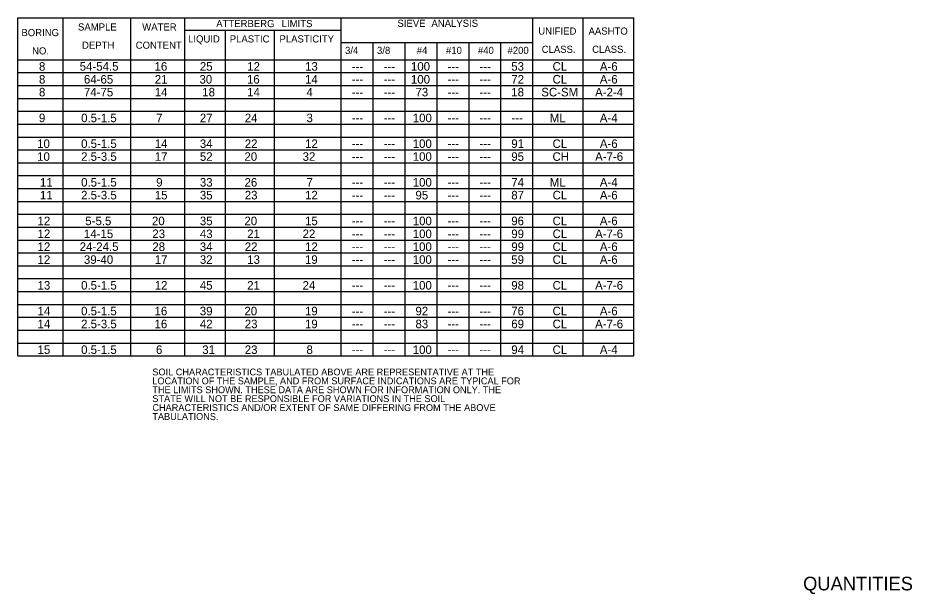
# Model space of a CAD drawing. Extents: x 1197542 to 1207464, y 185022 to 237324.
# Drawn here: x 1206911.8 to 1207068.6, y 185021.7 to 185122.8 of the extents above; entities that cross this region are included whole.
import ezdxf

# ---------------------------------------------------------------- set-up
doc = ezdxf.new("R2010")
doc.units = 0
doc.layers.add('R_Annotation', color=7, linetype='Continuous')
doc.layers.add('R_No Plot', color=7, linetype='Continuous')

msp = doc.modelspace()

# ---------------------------------------------------------------- linework, layer by layer
at = {"layer": 'R_No Plot'}
for p, q in [((1206911.83, 185122.77), (1206911.83, 185122.77)), ((1206911.83, 185122.77), (1207019.8, 185122.77)), ((1206911.83, 185063.47), (1206911.83, 185122.77)), ((1206919.77, 185063.47), (1206919.77, 185122.77)), ((1206931.61, 185063.47), (1206931.61, 185122.77)), ((1206941.11, 185063.47), (1206941.11, 185122.77)), ((1206968.54, 185063.47), (1206968.54, 185122.77)), ((1207002.13, 185063.47), (1207002.13, 185122.77)), ((1207010.96, 185063.47), (1207010.96, 185122.77)), ((1207019.8, 185063.47), (1207019.8, 185122.77)), ((1206941.11, 185120.6), (1206968.54, 185120.6)), ((1206948.26, 185063.47), (1206948.26, 185120.6)), ((1206956.84, 185063.47), (1206956.84, 185120.6)), ((1206968.54, 185118.44), (1207002.13, 185118.44)), ((1206974.14, 185063.47), (1206974.14, 185118.44)), ((1206979.74, 185063.47), (1206979.74, 185118.44)), ((1206985.34, 185063.47), (1206985.34, 185118.44)), ((1206990.94, 185063.47), (1206990.94, 185118.44)), ((1206996.53, 185063.47), (1206996.53, 185118.44)), ((1206911.83, 185115.42), (1207019.8, 185115.42)), ((1207002.13, 185115.42), (1207019.8, 185115.42)), ((1206911.83, 185113.16), (1207019.8, 185113.16)), ((1206911.83, 185110.9), (1207019.8, 185110.9)), ((1206911.83, 185108.64), (1207019.8, 185108.64)), ((1206911.83, 185106.39), (1207019.8, 185106.39)), ((1206911.83, 185104.13), (1207019.8, 185104.13)), ((1206911.83, 185101.87), (1207019.8, 185101.87)), ((1206911.83, 185099.61), (1207019.8, 185099.61)), ((1206911.83, 185097.35), (1207019.8, 185097.35)), ((1206911.83, 185095.09), (1207019.8, 185095.09)), ((1206911.83, 185092.83), (1207019.8, 185092.83)), ((1206911.83, 185090.57), (1207019.8, 185090.57)), ((1206911.83, 185088.32), (1207019.8, 185088.32)), ((1206911.83, 185086.06), (1207019.8, 185086.06)), ((1206911.83, 185083.8), (1207019.8, 185083.8)), ((1206911.83, 185081.54), (1207019.8, 185081.54)), ((1206911.83, 185079.28), (1207019.8, 185079.28)), ((1206911.83, 185077.02), (1207019.8, 185077.02)), ((1206911.83, 185074.76), (1207019.8, 185074.76)), ((1206911.83, 185072.5), (1207019.8, 185072.5)), ((1206911.83, 185070.25), (1207019.8, 185070.25)), ((1206911.83, 185067.99), (1207019.8, 185067.99)), ((1206911.83, 185065.73), (1207019.8, 185065.73)), ((1206911.83, 185063.47), (1207019.8, 185063.47))]:
    msp.add_line(p, q, dxfattribs=at)

# ---------------------------------------------------------------- texts
at = {"layer": 'R_Annotation'}
msp.add_text('QUANTITIES', height=2.4, rotation=360, dxfattribs=at).set_placement((1207049.51, 185022.34))
at = {"layer": 'R_No Plot'}
for s, height, p in [('ATTERBERG', 1.25, (1206946.61, 185121.14)), ('LIMITS', 1.25, (1206958.09, 185121.14)), ('SIEVE', 1.25, (1206978.38, 185121.19)), ('ANALYSIS', 1.25, (1206984.34, 185121.19)), ('BORING', 1.25, (1206912.45, 185119.56)), ('SAMPLE', 1.25, (1206922.38, 185120.55)), ('WATER', 1.25, (1206933.63, 185120.55)), ('UNIFIED', 1.25, (1207003.07, 185119.83)), ('AASHTO', 1.25, (1207011.89, 185119.83)), ('LIQUID', 1.25, (1206941.67, 185118.45)), ('PLASTIC', 1.25, (1206948.98, 185118.45)), ('PLASTICITY', 1.25, (1206957.7, 185118.45)), ('NO.', 1.25, (1206914.32, 185116.35)), ('DEPTH', 1.25, (1206923.08, 185117.35)), ('CONTENT', 1.25, (1206932.49, 185117.35)), ('3/4', 1.25, (1206969.2, 185116.44)), ('3/8', 1.25, (1206974.8, 185116.44)), ('#4', 1.25, (1206981.77, 185116.44)), ('#10', 1.25, (1206986.89, 185116.44)), ('#40', 1.25, (1206992.49, 185116.44)), ('#200', 1.25, (1206997.68, 185116.44)), ('CLASS.', 1.25, (1207003.67, 185116.63)), ('CLASS.', 1.25, (1207012.52, 185116.63)), ('8', 1.5, (1206915.53, 185113.5)), ('54-54.5', 1.5, (1206922.67, 185113.5)), ('16', 1.5, (1206935.79, 185113.5)), ('25', 1.5, (1206943.74, 185113.5)), ('12', 1.5, (1206952.04, 185113.5)), ('13', 1.5, (1206962.18, 185113.5)), ('100', 1.5, (1206980.75, 185113.5)), ('53', 1.5, (1206998.34, 185113.5)), ('CL', 1.5, (1207005.58, 185113.5)), ('A-6', 1.5, (1207013.87, 185113.5)), ('8', 1.5, (1206915.53, 185111.24)), ('64-65', 1.5, (1206923.41, 185111.24)), ('21', 1.5, (1206935.83, 185111.24)), ('30', 1.5, (1206943.67, 185111.24)), ('16', 1.5, (1206952, 185111.24)), ('14', 1.5, (1206962.18, 185111.24)), ('---', 1.5, (1206970.37, 185113.5)), ('---', 1.5, (1206975.97, 185113.5)), ('100', 1.5, (1206980.75, 185111.24)), ('---', 1.5, (1206987.17, 185113.5)), ('---', 1.5, (1206992.76, 185113.5)), ('72', 1.5, (1206998.34, 185111.24)), ('CL', 1.5, (1207005.58, 185111.24)), ('A-6', 1.5, (1207013.87, 185111.24)), ('---', 1.5, (1206970.37, 185111.24)), ('---', 1.5, (1206975.97, 185111.24)), ('---', 1.5, (1206987.17, 185111.24)), ('---', 1.5, (1206992.76, 185111.24)), ('8', 1.5, (1206915.53, 185108.99)), ('74-75', 1.5, (1206923.41, 185108.99)), ('14', 1.5, (1206935.83, 185108.99)), ('18', 1.5, (1206944.16, 185108.99)), ('14', 1.5, (1206952.04, 185108.99)), ('4', 1.5, (1206962.43, 185108.99)), ('---', 1.5, (1206970.37, 185108.99)), ('---', 1.5, (1206975.97, 185108.99)), ('73', 1.5, (1206981.54, 185108.99)), ('---', 1.5, (1206987.17, 185108.99)), ('---', 1.5, (1206992.76, 185108.99)), ('18', 1.5, (1206998.34, 185108.99)), ('SC-SM', 1.5, (1207003.6, 185108.99)), ('A-2-4', 1.5, (1207013.04, 185108.99)), ('9', 1.5, (1206915.52, 185104.47)), ('0.5-1.5', 1.5, (1206922.92, 185104.47)), ('7', 1.5, (1206936.08, 185104.47)), ('27', 1.5, (1206943.74, 185104.47)), ('24', 1.5, (1206951.61, 185104.47)), ('3', 1.5, (1206962.43, 185104.47)), ('---', 1.5, (1206970.37, 185104.47)), ('---', 1.5, (1206975.97, 185104.47)), ('100', 1.5, (1206981.06, 185104.47)), ('---', 1.5, (1206987.17, 185104.47)), ('---', 1.5, (1206992.76, 185104.47)), ('---', 1.5, (1206998.36, 185104.47)), ('ML', 1.5, (1207005.09, 185104.47)), ('A-4', 1.5, (1207013.87, 185104.47)), ('10', 1.5, (1206915.21, 185099.95)), ('0.5-1.5', 1.5, (1206922.92, 185099.95)), ('14', 1.5, (1206935.83, 185099.95)), ('34', 1.5, (1206943.74, 185099.95)), ('22', 1.5, (1206951.61, 185099.95)), ('12', 1.5, (1206962.18, 185099.95)), ('---', 1.5, (1206970.37, 185099.95)), ('---', 1.5, (1206975.97, 185099.95)), ('100', 1.5, (1206981.06, 185099.95)), ('---', 1.5, (1206987.17, 185099.95)), ('---', 1.5, (1206992.76, 185099.95)), ('91', 1.5, (1206998.34, 185099.95)), ('CL', 1.5, (1207005.58, 185099.95)), ('A-6', 1.5, (1207013.87, 185099.95)), ('10', 1.5, (1206915.21, 185097.69)), ('2.5-3.5', 1.5, (1206922.92, 185097.69)), ('17', 1.5, (1206935.83, 185097.69)), ('52', 1.5, (1206943.74, 185097.69)), ('20', 1.5, (1206951.55, 185097.69)), ('32', 1.5, (1206961.75, 185097.69)), ('100', 1.5, (1206981.06, 185097.69)), ('95', 1.5, (1206998.34, 185097.69)), ('CH', 1.5, (1207005.57, 185097.69)), ('A-7-6', 1.5, (1207013.04, 185097.69)), ('---', 1.5, (1206970.37, 185097.69)), ('---', 1.5, (1206975.97, 185097.69)), ('---', 1.5, (1206987.17, 185097.69)), ('---', 1.5, (1206992.76, 185097.69)), ('11', 1.5, (1206915.7, 185093.17)), ('0.5-1.5', 1.5, (1206922.92, 185093.17)), ('9', 1.5, (1206936.08, 185093.17)), ('33', 1.5, (1206943.74, 185093.17)), ('26', 1.5, (1206951.57, 185093.17)), ('7', 1.5, (1206962.43, 185093.17)), ('100', 1.5, (1206981.06, 185093.17)), ('74', 1.5, (1206998.34, 185093.17)), ('ML', 1.5, (1207005.09, 185093.17)), ('A-4', 1.5, (1207013.87, 185093.17)), ('11', 1.5, (1206915.7, 185090.92)), ('2.5-3.5', 1.5, (1206922.92, 185090.92)), ('15', 1.5, (1206935.83, 185090.92)), ('35', 1.5, (1206943.74, 185090.92)), ('23', 1.5, (1206951.61, 185090.92)), ('12', 1.5, (1206962.18, 185090.92)), ('---', 1.5, (1206970.37, 185093.17)), ('---', 1.5, (1206975.97, 185093.17)), ('95', 1.5, (1206981.54, 185090.92)), ('---', 1.5, (1206987.17, 185093.17)), ('---', 1.5, (1206992.76, 185093.17)), ('87', 1.5, (1206998.34, 185090.92)), ('CL', 1.5, (1207005.58, 185090.92)), ('A-6', 1.5, (1207013.87, 185090.92)), ('---', 1.5, (1206970.37, 185090.92)), ('---', 1.5, (1206975.97, 185090.92)), ('---', 1.5, (1206987.17, 185090.92)), ('---', 1.5, (1206992.76, 185090.92)), ('12', 1.5, (1206915.28, 185086.4)), ('5-5.5', 1.5, (1206923.65, 185086.4)), ('20', 1.5, (1206935.34, 185086.4)), ('35', 1.5, (1206943.74, 185086.4)), ('20', 1.5, (1206951.55, 185086.4)), ('15', 1.5, (1206962.18, 185086.4)), ('100', 1.5, (1206981.06, 185086.4)), ('96', 1.5, (1206998.34, 185086.4)), ('CL', 1.5, (1207005.58, 185086.4)), ('A-6', 1.5, (1207013.87, 185086.4)), ('---', 1.5, (1206970.37, 185086.4)), ('---', 1.5, (1206975.97, 185086.4)), ('---', 1.5, (1206987.17, 185086.4)), ('---', 1.5, (1206992.76, 185086.4)), ('12', 1.5, (1206915.28, 185084.14)), ('14-15', 1.5, (1206923.41, 185084.14)), ('23', 1.5, (1206935.41, 185084.14)), ('43', 1.5, (1206943.74, 185084.14)), ('21', 1.5, (1206952.04, 185084.14)), ('22', 1.5, (1206961.75, 185084.14)), ('---', 1.5, (1206970.37, 185084.14)), ('---', 1.5, (1206975.97, 185084.14)), ('100', 1.5, (1206981.06, 185084.14)), ('---', 1.5, (1206987.17, 185084.14)), ('---', 1.5, (1206992.76, 185084.14)), ('99', 1.5, (1206998.34, 185084.14)), ('CL', 1.5, (1207005.58, 185084.14)), ('A-7-6', 1.5, (1207013.04, 185084.14)), ('12', 1.5, (1206915.28, 185081.88)), ('24-24.5', 1.5, (1206922.67, 185081.88)), ('28', 1.5, (1206935.41, 185081.88)), ('34', 1.5, (1206943.74, 185081.88)), ('22', 1.5, (1206951.61, 185081.88)), ('12', 1.5, (1206962.18, 185081.88)), ('100', 1.5, (1206981.06, 185081.88)), ('99', 1.5, (1206998.34, 185081.88)), ('CL', 1.5, (1207005.58, 185081.88)), ('A-6', 1.5, (1207013.87, 185081.88)), ('---', 1.5, (1206970.37, 185081.88)), ('---', 1.5, (1206975.97, 185081.88)), ('---', 1.5, (1206987.17, 185081.88)), ('---', 1.5, (1206992.76, 185081.88)), ('12', 1.5, (1206915.28, 185079.62)), ('39-40', 1.5, (1206923.41, 185079.62)), ('17', 1.5, (1206935.83, 185079.62)), ('32', 1.5, (1206943.74, 185079.62)), ('13', 1.5, (1206952.04, 185079.62)), ('19', 1.5, (1206962.17, 185079.62)), ('---', 1.5, (1206970.37, 185079.62)), ('---', 1.5, (1206975.97, 185079.62)), ('100', 1.5, (1206981.06, 185079.62)), ('---', 1.5, (1206987.17, 185079.62)), ('---', 1.5, (1206992.76, 185079.62)), ('59', 1.5, (1206998.34, 185079.62)), ('CL', 1.5, (1207005.58, 185079.62)), ('A-6', 1.5, (1207013.87, 185079.62)), ('13', 1.5, (1206915.28, 185075.1)), ('0.5-1.5', 1.5, (1206922.92, 185075.1)), ('12', 1.5, (1206935.83, 185075.1)), ('45', 1.5, (1206943.74, 185075.1)), ('21', 1.5, (1206952.04, 185075.1)), ('24', 1.5, (1206961.75, 185075.1)), ('---', 1.5, (1206970.37, 185075.1)), ('---', 1.5, (1206975.97, 185075.1)), ('100', 1.5, (1206981.06, 185075.1)), ('---', 1.5, (1206987.17, 185075.1)), ('---', 1.5, (1206992.76, 185075.1)), ('98', 1.5, (1206998.34, 185075.1)), ('CL', 1.5, (1207005.58, 185075.1)), ('A-7-6', 1.5, (1207013.04, 185075.1)), ('14', 1.5, (1206915.28, 185070.59)), ('0.5-1.5', 1.5, (1206922.92, 185070.59)), ('16', 1.5, (1206935.79, 185070.59)), ('39', 1.5, (1206943.73, 185070.59)), ('20', 1.5, (1206951.55, 185070.59)), ('19', 1.5, (1206962.17, 185070.59)), ('92', 1.5, (1206981.54, 185070.59)), ('76', 1.5, (1206998.34, 185070.59)), ('CL', 1.5, (1207005.58, 185070.59)), ('A-6', 1.5, (1207013.87, 185070.59)), ('---', 1.5, (1206970.37, 185070.59)), ('---', 1.5, (1206975.97, 185070.59)), ('---', 1.5, (1206987.17, 185070.59)), ('---', 1.5, (1206992.76, 185070.59)), ('14', 1.5, (1206915.28, 185068.33)), ('2.5-3.5', 1.5, (1206922.92, 185068.33)), ('16', 1.5, (1206935.79, 185068.33)), ('42', 1.5, (1206943.74, 185068.33)), ('23', 1.5, (1206951.61, 185068.33)), ('19', 1.5, (1206962.17, 185068.33)), ('---', 1.5, (1206970.37, 185068.33)), ('---', 1.5, (1206975.97, 185068.33)), ('83', 1.5, (1206981.54, 185068.33)), ('---', 1.5, (1206987.17, 185068.33)), ('---', 1.5, (1206992.76, 185068.33)), ('69', 1.5, (1206998.34, 185068.33)), ('CL', 1.5, (1207005.58, 185068.33)), ('A-7-6', 1.5, (1207013.04, 185068.33)), ('15', 1.5, (1206915.28, 185063.81)), ('0.5-1.5', 1.5, (1206922.92, 185063.81)), ('6', 1.5, (1206936.04, 185063.81)), ('31', 1.5, (1206944.16, 185063.81)), ('23', 1.5, (1206951.61, 185063.81)), ('8', 1.5, (1206962.43, 185063.81)), ('---', 1.5, (1206970.37, 185063.81)), ('---', 1.5, (1206975.97, 185063.81)), ('100', 1.5, (1206981.06, 185063.81)), ('---', 1.5, (1206987.17, 185063.81)), ('---', 1.5, (1206992.76, 185063.81)), ('94', 1.5, (1206998.34, 185063.81)), ('CL', 1.5, (1207005.58, 185063.81)), ('A-4', 1.5, (1207013.87, 185063.81)), ('SOIL CHARACTERISTICS TABULATED ABOVE ARE REPRESENTATIVE AT THE ', 1.2, (1206935.41, 185060.05)), ('LOCATION OF THE SAMPLE, AND FROM SURFACE INDICATIONS ARE TYPICAL FOR ', 1.2, (1206935.41, 185058.49)), ('THE LIMITS SHOWN. THESE DATA ARE SHOWN FOR INFORMATION ONLY. THE ', 1.2, (1206935.41, 185056.93)), ('STATE WILL NOT BE RESPONSIBLE FOR VARIATIONS IN THE SOIL ', 1.2, (1206935.41, 185055.37)), ('CHARACTERISTICS AND/OR EXTENT OF SAME DIFFERING FROM THE ABOVE ', 1.2, (1206935.41, 185053.8)), ('TABULATIONS.', 1.2, (1206935.41, 185052.24))]:
    msp.add_text(s, height=height, dxfattribs=at).set_placement(p)

doc.saveas('drawing.dxf')
